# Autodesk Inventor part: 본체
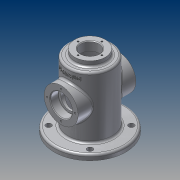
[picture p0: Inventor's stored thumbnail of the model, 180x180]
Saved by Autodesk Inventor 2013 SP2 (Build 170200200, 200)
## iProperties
Created: 2014-12
Part Number: 본체
Material: 알루미늄 6061
Document SubType Name: Modeling
Designer: CADB201
Density: 2.71 g/cm^3
Mass: 479.557 g
Surface Area: 607.444 cm^2
Volume: 176.958 cm^3
Author: CADB201
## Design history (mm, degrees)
node "작업 평면1"
sketch "스케치2"
  geometry: C1 r 32.5 at (0, 0); 1 further point
  constraints: 1 centre point, 1 coincident
  dimensions: "d3" = 65 diameter of C1
extrude "돌출1" new body sketch "스케치2" distance "d4" = 98; taper "d5" = 0 deg
fillet "모깎기1" dims "d6" = 3
sketch "스케치3"
  geometry: C1 r 27.5 at (0, 0); C2 r 52.5 at (0, 0); C3 r 32.5 at (0, 0) reference; 1 further point
  constraints: 2 centre point, 2 coincident
  dimensions: "d7" = 55 diameter of C1; "d8" = 105 diameter of C2
extrude "돌출2" cut sketch "스케치3" distance "d9" = 93; taper "d10" = 0 deg
extrude "돌출3" join sketch "스케치3" distance "d11" = 8; taper "d12" = 0 deg
node "작업 평면2"
sketch "스케치6"
  geometry: C1 r 25 at (0, 0); C2 r 16 at (0, 0); C3 r 12.5 at (0, 0); 1 further point
  constraints: 3 centre point, 3 coincident
  dimensions: "d14" = 50 diameter of C1; "d15" = 32 diameter of C2; "d16" = 25 diameter of C3
extrude "돌출4" join sketch "스케치6" stored distance "d17" = 8; taper "d18" = 0 deg
extrude "돌출5" cut sketch "스케치6" distance "d19" = 12; taper "d20" = 0 deg
extrude "돌출6" cut sketch "스케치6" stored distance "d21" = 12; taper "d22" = 0 deg
sketch "스케치7"
  geometry: C1 r 22.5 at (0, 0); C2 r 13.5 at (0, 0); 1 further point
  constraints: 2 centre point, 2 coincident
  dimensions: "d23" = 45 diameter of C1; "d24" = 27 diameter of C2
extrude "돌출7" join sketch "스케치7" distance "d25" = 8; taper "d26" = 0 deg
sketch "스케치8"
  geometry: C1 r 13.5 at (0, 0); 1 further point
  constraints: 1 centre point, 1 coincident
  dimensions: "d27" = 27 diameter of C1
extrude "돌출8" cut sketch "스케치8" stored distance "d28" = 27 (= d27); taper "d29" = 0 deg
fillet "모깎기2" dims "d30" = 0.3
fillet "모깎기3" dims "d31" = 3
sketch "스케치9"
  geometry: L1 (0, 0)-(30.406, 30.406); L2 (0, 0)-(43, 0); 1 further point
  constraints: 4 end point, 1 coincident, 1 equal length, 1 horizontal
  dimensions: "d33" = 43 distance of L1.start L1.end; "d34" = 45 deg angle of L2 L1
hole "구멍1" sketch "스케치9" at (30.406, 30.406) diameter "d35" = 8; stored, may be unused: countersink angle "d39" = 90 deg, drill point angle "d41" = 118 deg; dims "d36" = 6, "d37" = 4, "d38" = 2, "d40" = 8
sketch "스케치10"
  geometry: 2 further points
  constraints: 1 vertical alignment
  dimensions: "d45" = 17.5 distance of point (0, 17.5) point (0, 0)
hole "구멍2" sketch "스케치10" at (0, 17.5) diameter "d46" = 2.459; stored, may be unused: countersink angle "d50" = 90 deg, drill point angle "d52" = 118 deg; dims "d47" = 6, "d48" = 4, "d49" = 2, "d51" = 8
sketch "스케치11"
  geometry: 2 further points
  constraints: 1 horizontal alignment
  dimensions: "d56" = 20.5 distance of point (20.5, 0) point (0, 0)
hole "구멍3" sketch "스케치11" at (20.5, 0) diameter "d57" = 2.459; stored, may be unused: countersink angle "d61" = 90 deg, drill point angle "d63" = 118 deg; dims "d58" = 6, "d59" = 4, "d60" = 2, "d62" = 8
chamfer "모따기1" distance "d67" = 1; stored, may be unused: second distance "d68" = 2, angle "d69" = 45 deg
node "작업 평면3"
sketch "스케치13"
  geometry: L1 (-29.5, 43)-(29.5, 43) reference; 2 further points
  constraints: 1 vertical alignment, 1 other
  dimensions: "d71" = 9 distance from line of L1 point (0, 34)
feature "엠보싱1" sketch "스케치13" dims "d72" = 1, "d73" = 0
node "솔리드1"
mirror "대칭1"
pattern_circular "원형 패턴1" dims angle "d43" = 360 deg
pattern_circular "원형 패턴2" dims angle "d54" = 360 deg
pattern_circular "원형 패턴3" dims angle "d65" = 360 deg
mirror "대칭2"
other parameters: "d2" = -55, "d13" = 42.5, "d70" = -33
